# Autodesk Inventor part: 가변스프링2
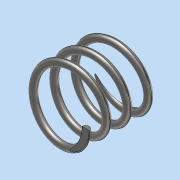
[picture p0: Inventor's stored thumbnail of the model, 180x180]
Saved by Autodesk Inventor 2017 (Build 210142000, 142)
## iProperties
Part Number: 가변스프링2
Material: 스테인레스 스틸
Document SubType Name: Modeling
Designer: MRC
Density: 8 g/cm^3
Appearance: 반연마
Mass: 4.57051 g
Surface Area: 11.8498 cm^2
Volume: 0.571314 cm^3
Author: MRC
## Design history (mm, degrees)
sketch "스케치1"
  geometry: L1 (0, 0)-(0, 19.5); L2 (0, 19.5)-(9, 19.5); L3 (0, 0)-(9, 0); C1 r 1 at (9, 0)
  constraints: 6 end point, 1 centre point, 1 coincident, 1 parallel, 1 perpendicular, 1 vertical
  dimensions: "d0" = 19.5 distance of L1.start L1.end (derived); "d1" = 9 distance of L1.end L2.end; "d2" = 9 distance of L1.start L3.end; "d3" = 2 diameter of C1
feature "코일1" sketch "스케치1" pitch "d4" = 10; turns "d6" = 5; dims "d5" = 30, "d7" = 0, angle "d8" = 90 deg, angle "d9" = 90 deg, "d10" = 0, "d11" = 0
sketch "스케치2"
  geometry: L1 (19.5, 15.094)-(0, 15.094); L2 (0, 15.094)-(0, -15.094); L3 (0, -15.094)-(19.5, -15.094); L4 (19.5, -15.094)-(19.5, 15.094); 3 further points
  constraints: 8 end point, 2 midpoint, 2 parallel, 1 coincident, 1 horizontal, 1 horizontal alignment, 1 perpendicular
  dimensions: "d12" = 19.5 distance of L2.end L3.end (= d0); "d13" = 30.18785 distance of L3.end L1.start
extrude "돌출1" sketch "스케치2" stored distance "d14" = 0; taper "d15" = 0 deg
node "솔리드1"
